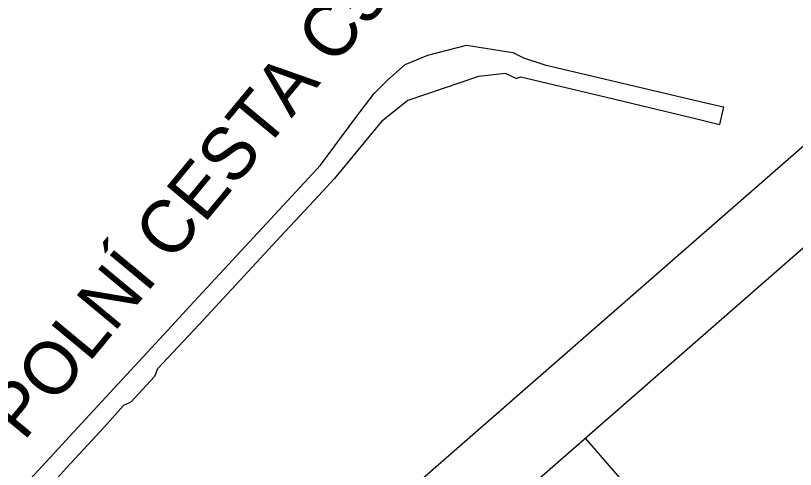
# Model space of a CAD drawing. Extents: x -482105 to -477964, y -1113879 to -1109998.
# Drawn here: x -479200 to -478683, y -1110991 to -1110690 of the extents above; entities that cross this region are included whole.
import ezdxf

# ---------------------------------------------------------------- set-up
doc = ezdxf.new("R2010")
doc.units = 0
for name, color, linetype in [('hranice staveniště', 7, 'Continuous'), ('legenda', 7, 'Continuous'), ('rozpiska', 7, 'Continuous'), ('SO', 7, 'Continuous')]:
    doc.layers.add(name, color=color, linetype=linetype)

msp = doc.modelspace()

# ---------------------------------------------------------------- linework, layer by layer
at = {"layer": 'hranice staveniště'}
for p, q in [((-478926.41, -1110716.57), (-478900.83, -1110709.96)), ((-478900.83, -1110709.96), (-478870.23, -1110714.79)), ((-478870.23, -1110714.79), (-478863.08, -1110718.17)), ((-478941.58, -1110722.7), (-478926.41, -1110716.57)), ((-478863.08, -1110718.17), (-478848.99, -1110722.86)), ((-478953.02, -1110732.83), (-478941.58, -1110722.7)), ((-478848.99, -1110722.86), (-478742.22, -1110748.04)), ((-478892.84, -1110730.71), (-478939.7, -1110746.45)), ((-478875, -1110728.57), (-478892.84, -1110730.71)), ((-478867.85, -1110732.01), (-478875, -1110728.57)), ((-478808.01, -1110744.42), (-478796.02, -1110747.3)), ((-478796.02, -1110747.3), (-478748.04, -1110758.79)), ((-478742.22, -1110748.04), (-478730.5, -1110750.81)), ((-478730.5, -1110750.81), (-478733.07, -1110762.35)), ((-478748.04, -1110758.79), (-478733.07, -1110762.35)), ((-479064.51, -1110861.44), (-479011.44, -1110804.15)), ((-478996.46, -1110806.9), (-479001.99, -1110812.85)), ((-479001.99, -1110812.85), (-479024.16, -1110836.68)), ((-479024.16, -1110836.68), (-479051.16, -1110865.72)), ((-479081.7, -1110880), (-479064.51, -1110861.44)), ((-479051.16, -1110865.72), (-479078.47, -1110895.09)), ((-479098.94, -1110898.61), (-479081.7, -1110880)), ((-479137.53, -1110940.28), (-479098.94, -1110898.61)), ((-479198.33, -1111005.91), (-479137.53, -1110940.28)), ((-479140.91, -1110962.82), (-479166.07, -1110989.97)), ((-479166.07, -1110989.97), (-479199.94, -1111026.53))]:
    msp.add_line(p, q, dxfattribs=at)
for points in [[(-478867.85, -1110732.01), (-478864.85, -1110730.79), (-478808.01, -1110744.42)], [(-478974.22, -1110757.86), (-478962.21, -1110741.84), (-478953.02, -1110732.83)], [(-478939.7, -1110746.45), (-478957.17, -1110760.36), (-478988.68, -1110798.53), (-478996.46, -1110806.9)], [(-479011.44, -1110804.15), (-478997.69, -1110789.32), (-478974.22, -1110757.86)], [(-479078.47, -1110895.09), (-479105.77, -1110924.31), (-479107.7, -1110929.38), (-479123.6, -1110946.39), (-479128.41, -1110948.67), (-479140.91, -1110962.82)]]:
    msp.add_lwpolyline(points, dxfattribs=at)
at = {"layer": 'legenda'}
msp.add_lwpolyline([(-481125.94, -1113843.42), (-479562.41, -1112479.24), (-479722.14, -1112296.17), (-478939.33, -1111613.17), (-479240.6, -1111267.87), (-478575.93, -1110687.94), (-479060.34, -1110136.67), (-481297.06, -1112088.2), (-481198.69, -1112200.95), (-481971.04, -1112874.82)], close=True, dxfattribs=at)
at = {"layer": 'rozpiska'}
for p, q in [((-478445.17, -1110641.6), (-479160.98, -1111266.2)), ((-478445.17, -1110641.6), (-479160.98, -1111266.2)), ((-478690.42, -1111121.03), (-478821.91, -1110970.34))]:
    msp.add_line(p, q, dxfattribs=at)

# ---------------------------------------------------------------- texts
at = {"layer": 'SO'}
msp.add_text('SO 101 HLAVNÍ POLNÍ CESTA C5 - 2. ČÁST', height=35, rotation=50.3503, dxfattribs=at).set_placement((-479420.33, -1111245.25))

doc.saveas('drawing.dxf')
